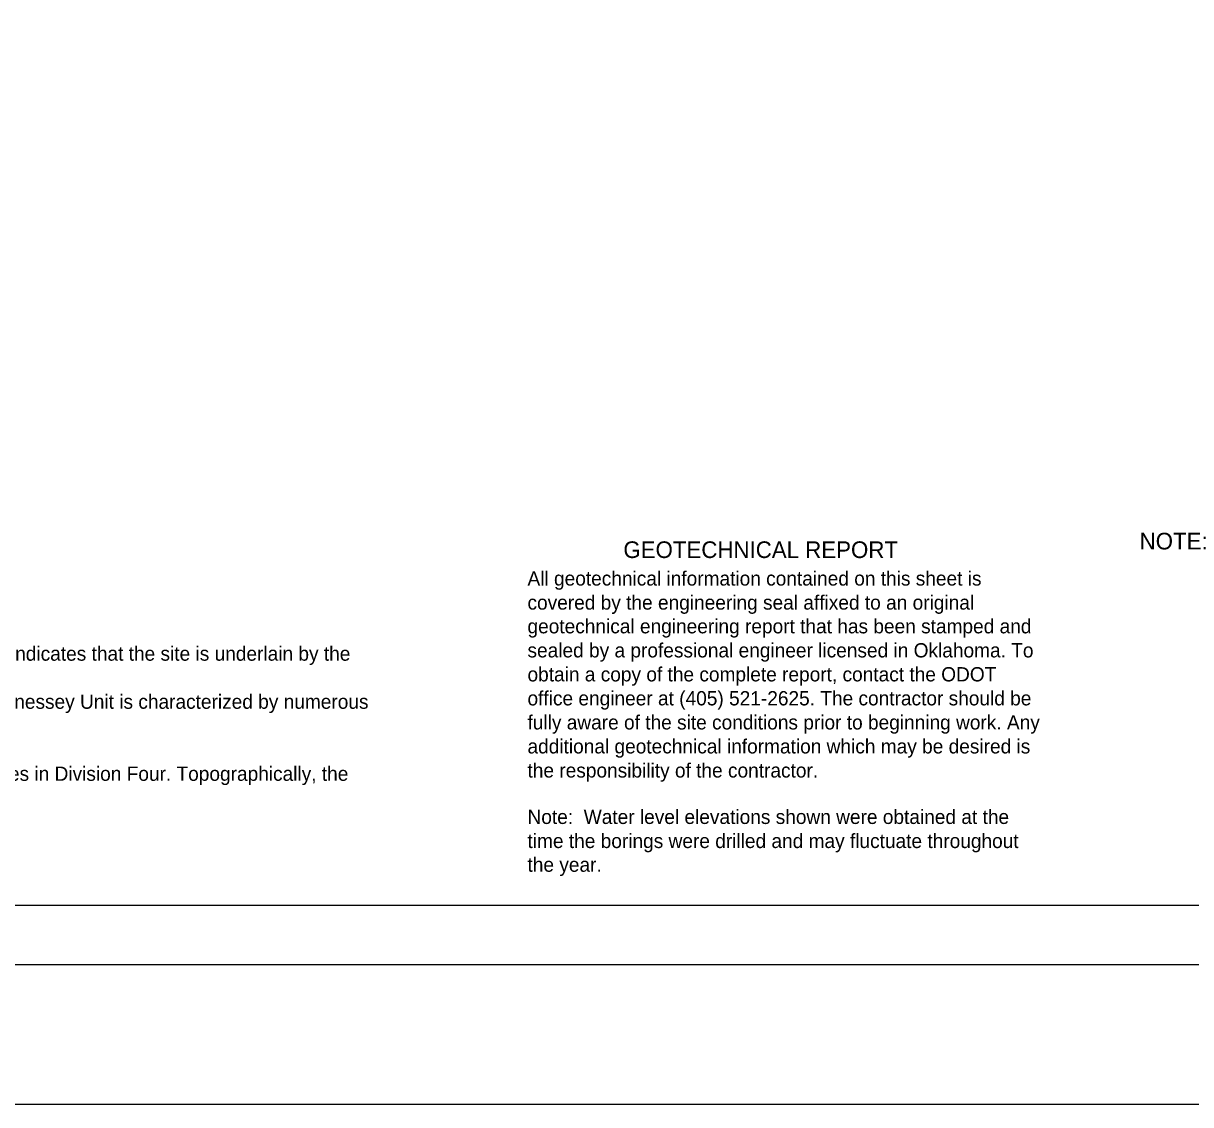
# Model space of a CAD drawing. Extents: x 2150148.6 to 2150220.1, y 143803.7 to 143875.1.
# Drawn here: x 2150182.61 to 2150195.7, y 143835.59 to 143847.71 of the extents above; entities that cross this region are included whole.
import ezdxf

# ---------------------------------------------------------------- set-up
doc = ezdxf.new("R2010")
doc.units = 0
for name, color, linetype in [('SHT_Plot_Shape_Full', 7, 'Continuous'), ('SHT_Plot_Shape_Half', 7, 'Continuous'), ('SHT_Sheet_Border', 7, 'Continuous'), ('Text', 7, 'Continuous')]:
    doc.layers.add(name, color=color, linetype=linetype)

msp = doc.modelspace()

# ---------------------------------------------------------------- linework, layer by layer
at = {"layer": 'SHT_Plot_Shape_Full'}
msp.add_lwpolyline([(2150163.596, 143867.587), (2150211.596, 143867.587), (2150211.596, 143835.587), (2150163.596, 143835.587)], close=True, dxfattribs=at)
at = {"layer": 'SHT_Plot_Shape_Half'}
msp.add_lwpolyline([(2150165.779, 143866.487), (2150211.112, 143866.487), (2150211.112, 143837.154), (2150165.779, 143837.154)], close=True, dxfattribs=at)
at = {"layer": 'SHT_Sheet_Border'}
msp.add_lwpolyline([(2150210.379, 143837.82), (2150168.379, 143837.82), (2150168.379, 143865.82), (2150210.379, 143865.82)], close=True, dxfattribs=at)

# ---------------------------------------------------------------- texts
at = {"layer": 'Text'}
for s, height, p in [('NOTE:', 0.1867, (2150195.13, 143841.814)), ('GEOTECHNICAL REPORT', 0.18667, (2150189.342, 143841.718)), ('All geotechnical information contained on this sheet is ', 0.16, (2150188.267, 143841.409)), ('covered by the engineering seal affixed to an original ', 0.16, (2150188.267, 143841.139)), ('geotechnical engineering report that has been stamped and ', 0.16, (2150188.267, 143840.873)), ('  “Division Four” of the “Engineering Classification of Geological Materials”, published by the Oklahoma Department of Transportation (ODOT) indicates that the site is underlain by the ', 0.159999, (2150169.026, 143840.566)), ('sealed by a professional engineer licensed in Oklahoma. To ', 0.16, (2150188.267, 143840.603)), ('obtain a copy of the complete report, contact the ODOT ', 0.16, (2150188.267, 143840.334)), ('  This unit consists of red platy to blocky clay shales and mudstone. The mudstones are hard and appear blocky. The red clay shale of the Hennessey Unit is characterized by numerous ', 0.159999, (2150169.026, 143840.027)), ('office engineer at (405) 521-2625. The contractor should be ', 0.16, (2150188.267, 143840.065)), ('fully aware of the site conditions prior to beginning work. Any ', 0.16, (2150188.267, 143839.795)), ('additional geotechnical information which may be desired is ', 0.16, (2150188.267, 143839.526)), ('  The Hennessey Unit outcrops in a 5- to 15-mile north-south band across Grant, Garfield, Kingfisher, Logan, Canadian, and Oklahoma Counties in Division Four. Topographically, the ', 0.159999, (2150169.026, 143839.219)), ('the responsibility of the contractor.', 0.16, (2150188.267, 143839.256)), ('Note:  Water level elevations shown were obtained at the ', 0.16, (2150188.267, 143838.735)), ('time the borings were drilled and may fluctuate throughout ', 0.16, (2150188.267, 143838.465)), ('the year.', 0.16, (2150188.267, 143838.199))]:
    msp.add_text(s, height=height, dxfattribs=at).set_placement(p)

doc.saveas('drawing.dxf')
